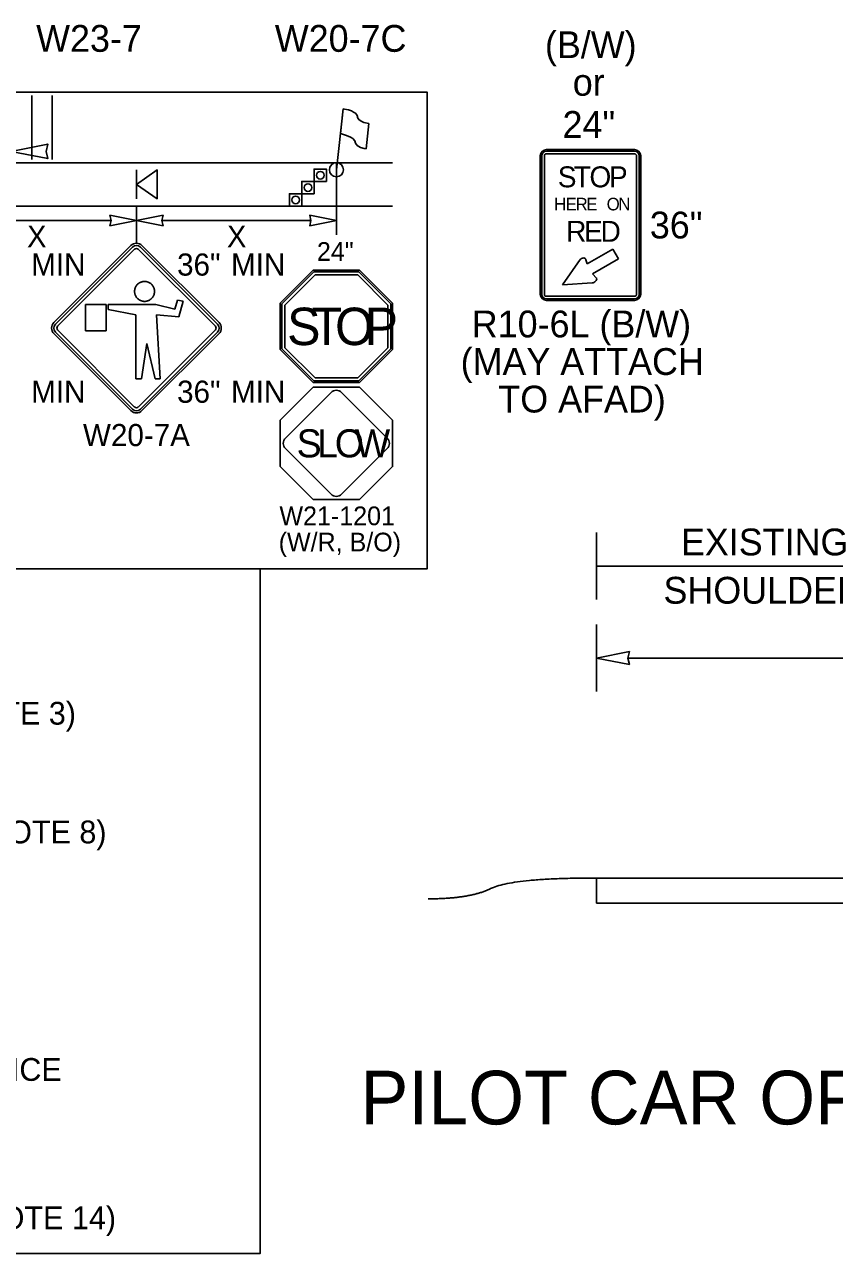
# Model space of a CAD drawing. Extents: x 99999.1 to 100095.7, y 99995 to 100010.7.
# Drawn here: x 100042.586 to 100045, y 100001.176 to 100004.84 of the extents above; entities that cross this region are included whole.
import ezdxf

# ---------------------------------------------------------------- set-up
doc = ezdxf.new("R2010")
doc.units = 0
for name, color, linetype in [('RD_ED_ShoulderPavedEdge', 7, 'Continuous'), ('RD_MK_LineEdgeWhite', 7, 'Continuous'), ('SH_DE_DetailHeading1Text', 7, 'Continuous'), ('TR_SN_ConstructionSigns', 7, 'Continuous'), ('TR_WZ_FlaggingStation', 7, 'Continuous'), ('TR_WZ_PortableSignMountBlk-Org', 7, 'Continuous'), ('TR_WZ_TrafficCone', 7, 'Continuous'), ('TR_WZ_WorkZoneDetails', 7, 'Continuous'), ('TR_WZ_WorkZoneTextCurrent', 7, 'Continuous')]:
    doc.layers.add(name, color=color, linetype=linetype)

msp = doc.modelspace()

# ---------------------------------------------------------------- linework, layer by layer
at = {"layer": 'RD_ED_ShoulderPavedEdge'}
msp.add_line((100040.2, 100004.2992), (100043.6825, 100004.2992), dxfattribs=at)
at = {"layer": 'RD_MK_LineEdgeWhite'}
msp.add_line((100040.2, 100004.4284), (100043.6825, 100004.4284), dxfattribs=at)
at = {"layer": 'TR_SN_ConstructionSigns'}
for p, q in [((100044.4041, 100004.4676), (100044.1416, 100004.4676)), ((100044.1416, 100004.4676), (100044.4041, 100004.4676)), ((100044.4041, 100004.4676), (100044.1416, 100004.4676)), ((100044.1229, 100004.4489), (100044.1229, 100004.0364)), ((100044.1229, 100004.0364), (100044.1229, 100004.4489)), ((100044.1229, 100004.4489), (100044.1229, 100004.0364)), ((100044.1276, 100004.4489), (100044.1276, 100004.0364)), ((100044.1354, 100004.0364), (100044.1354, 100004.4489)), ((100044.4041, 100004.4629), (100044.1416, 100004.4629)), ((100044.1416, 100004.4551), (100044.4041, 100004.4551)), ((100044.4104, 100004.4489), (100044.4104, 100004.0364)), ((100044.4182, 100004.0364), (100044.4182, 100004.4489)), ((100044.4229, 100004.0364), (100044.4229, 100004.4489)), ((100044.4229, 100004.4489), (100044.4229, 100004.0364)), ((100044.4229, 100004.0364), (100044.4229, 100004.4489)), ((100042.9031, 100004.1813), (100042.6734, 100003.9516)), ((100042.9076, 100004.1768), (100042.6779, 100003.9471)), ((100043.161, 100003.9471), (100042.9313, 100004.1768)), ((100043.1656, 100003.9516), (100042.9359, 100004.1813)), ((100044.3396, 100004.1707), (100044.263, 100004.1265)), ((100044.356, 100004.1423), (100044.3396, 100004.1707)), ((100042.6843, 100003.9407), (100042.914, 100004.1704)), ((100042.9249, 100004.1704), (100043.1546, 100003.9407)), ((100044.2424, 100004.1403), (100044.1898, 100004.0646)), ((100044.263, 100004.1265), (100044.2592, 100004.1391)), ((100044.2786, 100004.0976), (100044.356, 100004.1423)), ((100043.446, 100004.1079), (100043.3479, 100004.0098)), ((100043.4482, 100004.1026), (100043.3531, 100004.0076)), ((100043.5847, 100004.1079), (100043.446, 100004.1079)), ((100043.5825, 100004.1026), (100043.4482, 100004.1026)), ((100043.6775, 100004.0076), (100043.5825, 100004.1026)), ((100043.6828, 100004.0098), (100043.5847, 100004.1079)), ((100044.2909, 100004.0839), (100044.2786, 100004.0976)), ((100042.9188, 100004.0612), (100042.9179, 100004.0598)), ((100042.9197, 100004.0625), (100042.9188, 100004.0612)), ((100042.9207, 100004.0637), (100042.9197, 100004.0625)), ((100042.9217, 100004.0649), (100042.9207, 100004.0637)), ((100042.9228, 100004.066), (100042.9217, 100004.0649)), ((100042.924, 100004.0671), (100042.9228, 100004.066)), ((100042.9252, 100004.0681), (100042.924, 100004.0671)), ((100042.9264, 100004.069), (100042.9252, 100004.0681)), ((100042.9278, 100004.0699), (100042.9264, 100004.069)), ((100042.9291, 100004.0707), (100042.9278, 100004.0699)), ((100042.9306, 100004.0714), (100042.9291, 100004.0707)), ((100042.932, 100004.0721), (100042.9306, 100004.0714)), ((100042.9335, 100004.0727), (100042.932, 100004.0721)), ((100042.935, 100004.0731), (100042.9335, 100004.0727)), ((100042.9365, 100004.0736), (100042.935, 100004.0731)), ((100042.9381, 100004.0739), (100042.9365, 100004.0736)), ((100042.9396, 100004.0742), (100042.9381, 100004.0739)), ((100042.9412, 100004.0743), (100042.9396, 100004.0742)), ((100042.9428, 100004.0744), (100042.9412, 100004.0743)), ((100042.9444, 100004.0744), (100042.9428, 100004.0744)), ((100042.9459, 100004.0743), (100042.9444, 100004.0744)), ((100042.9475, 100004.0742), (100042.9459, 100004.0743)), ((100042.949, 100004.0739), (100042.9475, 100004.0742)), ((100042.9506, 100004.0736), (100042.949, 100004.0739)), ((100042.9521, 100004.0731), (100042.9506, 100004.0736)), ((100042.9536, 100004.0727), (100042.9521, 100004.0731)), ((100042.9551, 100004.0721), (100042.9536, 100004.0727)), ((100042.9565, 100004.0714), (100042.9551, 100004.0721)), ((100042.9579, 100004.0707), (100042.9565, 100004.0714)), ((100042.9593, 100004.0699), (100042.9579, 100004.0707)), ((100042.9606, 100004.069), (100042.9593, 100004.0699)), ((100042.9619, 100004.0681), (100042.9606, 100004.069)), ((100042.9631, 100004.0671), (100042.9619, 100004.0681)), ((100042.9643, 100004.066), (100042.9631, 100004.0671)), ((100042.9654, 100004.0649), (100042.9643, 100004.066)), ((100042.9664, 100004.0637), (100042.9654, 100004.0649)), ((100042.9674, 100004.0625), (100042.9664, 100004.0637)), ((100042.9683, 100004.0612), (100042.9674, 100004.0625)), ((100042.9691, 100004.0598), (100042.9683, 100004.0612)), ((100043.3619, 100004.004), (100043.4518, 100004.0939)), ((100043.4518, 100004.0939), (100043.5789, 100004.0939)), ((100043.5789, 100004.0939), (100043.6688, 100004.004)), ((100044.1898, 100004.0646), (100044.2776, 100004.0707)), ((100042.914, 100004.0479), (100042.9138, 100004.0463)), ((100042.9138, 100004.0463), (100042.9138, 100004.0447)), ((100042.9138, 100004.0447), (100042.9138, 100004.0432)), ((100042.9138, 100004.0432), (100042.914, 100004.0416)), ((100042.9142, 100004.0495), (100042.914, 100004.0479)), ((100042.914, 100004.0416), (100042.9142, 100004.04)), ((100042.9145, 100004.051), (100042.9142, 100004.0495)), ((100042.9142, 100004.04), (100042.9145, 100004.0385)), ((100042.9149, 100004.0525), (100042.9145, 100004.051)), ((100042.9145, 100004.0385), (100042.9149, 100004.0369)), ((100042.9153, 100004.054), (100042.9149, 100004.0525)), ((100042.9149, 100004.0369), (100042.9153, 100004.0354)), ((100042.9159, 100004.0555), (100042.9153, 100004.054)), ((100042.9153, 100004.0354), (100042.9159, 100004.0339)), ((100042.9165, 100004.057), (100042.9159, 100004.0555)), ((100042.9159, 100004.0339), (100042.9165, 100004.0324)), ((100042.9171, 100004.0584), (100042.9165, 100004.057)), ((100042.9165, 100004.0324), (100042.9171, 100004.031)), ((100042.9179, 100004.0598), (100042.9171, 100004.0584)), ((100042.9171, 100004.031), (100042.9179, 100004.0296)), ((100042.9179, 100004.0296), (100042.9188, 100004.0283)), ((100042.9188, 100004.0283), (100042.9197, 100004.027)), ((100042.9197, 100004.027), (100042.9207, 100004.0258)), ((100042.9207, 100004.0258), (100042.9217, 100004.0246)), ((100042.9217, 100004.0246), (100042.9228, 100004.0234)), ((100042.9643, 100004.0234), (100042.9654, 100004.0246)), ((100042.9654, 100004.0246), (100042.9664, 100004.0258)), ((100042.9664, 100004.0258), (100042.9674, 100004.027)), ((100042.9674, 100004.027), (100042.9683, 100004.0283)), ((100042.9683, 100004.0283), (100042.9691, 100004.0296)), ((100042.9699, 100004.0584), (100042.9691, 100004.0598)), ((100042.9691, 100004.0296), (100042.9699, 100004.031)), ((100042.9706, 100004.057), (100042.9699, 100004.0584)), ((100042.9699, 100004.031), (100042.9706, 100004.0324)), ((100042.9712, 100004.0555), (100042.9706, 100004.057)), ((100042.9706, 100004.0324), (100042.9712, 100004.0339)), ((100042.9718, 100004.054), (100042.9712, 100004.0555)), ((100042.9712, 100004.0339), (100042.9718, 100004.0354)), ((100042.9722, 100004.0525), (100042.9718, 100004.054)), ((100042.9718, 100004.0354), (100042.9722, 100004.0369)), ((100042.9726, 100004.051), (100042.9722, 100004.0525)), ((100042.9722, 100004.0369), (100042.9726, 100004.0385)), ((100042.9729, 100004.0495), (100042.9726, 100004.051)), ((100042.9726, 100004.0385), (100042.9729, 100004.04)), ((100042.9731, 100004.0479), (100042.9729, 100004.0495)), ((100042.9729, 100004.04), (100042.9731, 100004.0416)), ((100042.9732, 100004.0463), (100042.9731, 100004.0479)), ((100042.9731, 100004.0416), (100042.9732, 100004.0432)), ((100042.9733, 100004.0447), (100042.9732, 100004.0463)), ((100042.9732, 100004.0432), (100042.9733, 100004.0447)), ((100044.4041, 100004.0301), (100044.1416, 100004.0301)), ((100042.7675, 100004.0057), (100042.7675, 100003.9275)), ((100042.8296, 100004.0057), (100042.7675, 100004.0057)), ((100042.8296, 100003.9275), (100042.8296, 100004.0057)), ((100042.9768, 100004.0057), (100042.8354, 100004.0057)), ((100042.8354, 100004.0057), (100042.8354, 100003.9908)), ((100042.8354, 100003.9908), (100042.9175, 100003.9745)), ((100042.9228, 100004.0234), (100042.924, 100004.0224)), ((100042.924, 100004.0224), (100042.9252, 100004.0214)), ((100042.9252, 100004.0214), (100042.9264, 100004.0204)), ((100042.9264, 100004.0204), (100042.9278, 100004.0195)), ((100042.9278, 100004.0195), (100042.9291, 100004.0187)), ((100042.9291, 100004.0187), (100042.9306, 100004.018)), ((100042.9306, 100004.018), (100042.932, 100004.0173)), ((100042.932, 100004.0173), (100042.9335, 100004.0168)), ((100042.9335, 100004.0168), (100042.935, 100004.0163)), ((100042.935, 100004.0163), (100042.9365, 100004.0158)), ((100042.9365, 100004.0158), (100042.9381, 100004.0155)), ((100042.9381, 100004.0155), (100042.9396, 100004.0153)), ((100042.9396, 100004.0153), (100042.9412, 100004.0151)), ((100042.9412, 100004.0151), (100042.9428, 100004.015)), ((100042.9428, 100004.015), (100042.9444, 100004.015)), ((100042.9444, 100004.015), (100042.9459, 100004.0151)), ((100042.9459, 100004.0151), (100042.9475, 100004.0153)), ((100042.9475, 100004.0153), (100042.949, 100004.0155)), ((100042.949, 100004.0155), (100042.9506, 100004.0158)), ((100042.9506, 100004.0158), (100042.9521, 100004.0163)), ((100042.9521, 100004.0163), (100042.9536, 100004.0168)), ((100042.9536, 100004.0168), (100042.9551, 100004.0173)), ((100042.9551, 100004.0173), (100042.9565, 100004.018)), ((100042.9565, 100004.018), (100042.9579, 100004.0187)), ((100042.9579, 100004.0187), (100042.9593, 100004.0195)), ((100042.9593, 100004.0195), (100042.9606, 100004.0204)), ((100042.9606, 100004.0204), (100042.9619, 100004.0214)), ((100042.9619, 100004.0214), (100042.9631, 100004.0224)), ((100042.9631, 100004.0224), (100042.9643, 100004.0234)), ((100043.0341, 100003.9915), (100042.9768, 100004.0057)), ((100043.0421, 100004.0186), (100043.0341, 100003.9915)), ((100043.0586, 100004.0157), (100043.0421, 100004.0186)), ((100043.0462, 100003.9688), (100043.0586, 100004.0157)), ((100043.3479, 100004.0098), (100043.3479, 100003.8711)), ((100043.3531, 100004.0076), (100043.3531, 100003.8733)), ((100043.3619, 100003.8769), (100043.3619, 100004.004)), ((100043.6688, 100004.004), (100043.6688, 100003.8769)), ((100043.6775, 100003.8733), (100043.6775, 100004.0076)), ((100043.6828, 100003.8711), (100043.6828, 100004.0098)), ((100044.1416, 100004.0223), (100044.4041, 100004.0223)), ((100044.1416, 100004.0176), (100044.4041, 100004.0176)), ((100044.4041, 100004.0176), (100044.1416, 100004.0176)), ((100044.1416, 100004.0176), (100044.4041, 100004.0176)), ((100042.9175, 100003.9745), (100042.9175, 100003.7844)), ((100042.9902, 100003.7844), (100042.9794, 100003.9745)), ((100042.9794, 100003.9745), (100043.0462, 100003.9688)), ((100042.6734, 100003.9188), (100042.9031, 100003.6891)), ((100042.6779, 100003.9234), (100042.9076, 100003.6937)), ((100042.914, 100003.7), (100042.6843, 100003.9297)), ((100042.7675, 100003.9275), (100042.8296, 100003.9275)), ((100043.1546, 100003.9297), (100042.9249, 100003.7)), ((100042.9313, 100003.6937), (100043.161, 100003.9234)), ((100042.9359, 100003.6891), (100043.1656, 100003.9188)), ((100042.9341, 100003.7844), (100042.9503, 100003.8889)), ((100042.9503, 100003.8889), (100042.9753, 100003.7844)), ((100043.3479, 100003.8711), (100043.446, 100003.773)), ((100043.3531, 100003.8733), (100043.4482, 100003.7783)), ((100043.4518, 100003.787), (100043.3619, 100003.8769)), ((100043.6688, 100003.8769), (100043.5789, 100003.787)), ((100043.5825, 100003.7783), (100043.6775, 100003.8733)), ((100043.5847, 100003.773), (100043.6828, 100003.8711)), ((100042.9175, 100003.7844), (100042.9341, 100003.7844)), ((100042.9753, 100003.7844), (100042.9902, 100003.7844)), ((100043.446, 100003.773), (100043.5847, 100003.773)), ((100043.4482, 100003.7783), (100043.5825, 100003.7783)), ((100043.5789, 100003.787), (100043.4518, 100003.787)), ((100043.4996, 100003.7433), (100043.3637, 100003.6074)), ((100043.667, 100003.6074), (100043.5311, 100003.7433)), ((100043.3637, 100003.5759), (100043.4996, 100003.44)), ((100043.5311, 100003.44), (100043.667, 100003.5759))]:
    msp.add_line(p, q, dxfattribs=at)
msp.add_lwpolyline([(100043.6828, 100003.661), (100043.6828, 100003.5223), (100043.5847, 100003.4242), (100043.446, 100003.4242), (100043.3479, 100003.5223), (100043.3479, 100003.661), (100043.446, 100003.7591), (100043.5847, 100003.7591)], close=True, dxfattribs=at)
for centre, radius, start, end in [((100044.1416, 100004.4489), 0.0187, 90, 180), ((100044.1416, 100004.4489), 0.0187, 90, 180), ((100044.1416, 100004.4489), 0.0187, 90, 180), ((100044.4041, 100004.4489), 0.0187, 0, 90), ((100044.4041, 100004.4489), 0.0187, 0, 90), ((100044.4041, 100004.4489), 0.0187, 0, 90), ((100044.1416, 100004.4489), 0.0141, 90, 180), ((100044.1416, 100004.4489), 0.00625, 90, 180), ((100044.4041, 100004.4489), 0.0141, 0, 90), ((100044.4041, 100004.4489), 0.00625, 0, 90), ((100042.9195, 100004.1649), 0.0232, 45, 135), ((100042.9195, 100004.1649), 0.0168, 45, 135), ((100042.9195, 100004.1649), 0.00773, 45, 135), ((100044.1416, 100004.0364), 0.0187, 180, 270), ((100044.1416, 100004.0364), 0.0187, 180, 270), ((100044.1416, 100004.0364), 0.0187, 180, 270), ((100044.1416, 100004.0364), 0.0141, 180, 270), ((100044.1416, 100004.0364), 0.00625, 180, 270), ((100044.4041, 100004.0364), 0.0187, 270, 0), ((100044.4041, 100004.0364), 0.0187, 270, 0), ((100044.4041, 100004.0364), 0.0187, 270, 0), ((100044.4041, 100004.0364), 0.0141, 270, 0), ((100044.4041, 100004.0364), 0.00625, 270, 0), ((100042.6898, 100003.9352), 0.0232, 135, 225), ((100043.1492, 100003.9352), 0.0232, 315, 45), ((100042.6898, 100003.9352), 0.0168, 135, 225), ((100042.6898, 100003.9352), 0.00773, 135, 225), ((100043.1492, 100003.9352), 0.00773, 315, 45), ((100043.1492, 100003.9352), 0.0168, 315, 45), ((100043.5153, 100003.7275), 0.0223, 45, 135), ((100042.9195, 100003.7055), 0.00773, 225, 315), ((100042.9195, 100003.7055), 0.0232, 225, 315), ((100042.9195, 100003.7055), 0.0168, 225, 315), ((100043.3795, 100003.5916), 0.0223, 135, 225), ((100043.6512, 100003.5916), 0.0223, 315, 45), ((100043.5153, 100003.4558), 0.0223, 225, 315)]:
    msp.add_arc(centre, radius, start, end, dxfattribs=at)
for centre, major_axis, start_param, end_param in [((100044.2492, 100004.136), (0.00934, 0.00539), 5.977036, 8.198856), ((100044.2816, 100004.0789), (-0.00913, -0.00527), 0.771965, 3.092601)]:
    msp.add_ellipse(centre, major_axis=major_axis, ratio=0.700347, start_param=start_param, end_param=end_param, dxfattribs=at)
at = {"layer": 'TR_WZ_FlaggingStation'}
for p, q in [((100043.5154, 100004.4074), (100043.5361, 100004.5889)), ((100043.5277, 100004.5152), (100043.5361, 100004.5891)), ((100043.6123, 100004.5453), (100043.6037, 100004.4696)), ((100043.5277, 100004.5152), (100043.5277, 100004.5152))]:
    msp.add_line(p, q, dxfattribs=at)
for points in [[(100043.5361, 100004.5891), (100043.5398, 100004.5883), (100043.5514, 100004.5861), (100043.5603, 100004.5834), (100043.5665, 100004.5794), (100043.5721, 100004.5764), (100043.5757, 100004.572), (100043.5785, 100004.5669), (100043.5788, 100004.5629), (100043.5823, 100004.557), (100043.5892, 100004.5522), (100043.5973, 100004.5488), (100043.6123, 100004.5453)], [(100043.6037, 100004.4696), (100043.5985, 100004.4705), (100043.587, 100004.4735), (100043.5769, 100004.4803), (100043.5727, 100004.4871), (100043.5702, 100004.4938), (100043.5643, 100004.5008), (100043.5572, 100004.5048), (100043.546, 100004.5094), (100043.5277, 100004.5152)]]:
    msp.add_lwpolyline(points, dxfattribs=at)
msp.add_circle((100043.5154, 100004.4074), 0.021, dxfattribs=at)
at = {"layer": 'TR_WZ_PortableSignMountBlk-Org'}
msp.add_line((100042.9195, 100004.3208), (100042.9195, 100004.4069), dxfattribs=at)
msp.add_lwpolyline([(100042.9195, 100004.3638), (100042.9813, 100004.4069), (100042.9813, 100004.3208)], close=True, dxfattribs=at)
at = {"layer": 'TR_WZ_TrafficCone'}
for points in [[(100043.4491, 100004.4095), (100043.4858, 100004.4095), (100043.4858, 100004.3727), (100043.4491, 100004.3727), (100043.4491, 100004.4095)], [(100043.4491, 100004.3727), (100043.4858, 100004.3727), (100043.4858, 100004.4095), (100043.4491, 100004.4095), (100043.4491, 100004.3727)], [(100043.4123, 100004.3727), (100043.4491, 100004.3727), (100043.4491, 100004.336), (100043.4123, 100004.336), (100043.4123, 100004.3727)], [(100043.4123, 100004.336), (100043.4491, 100004.336), (100043.4491, 100004.3727), (100043.4123, 100004.3727), (100043.4123, 100004.336)], [(100043.3756, 100004.336), (100043.4123, 100004.336), (100043.4123, 100004.2992), (100043.3756, 100004.2992), (100043.3756, 100004.336)], [(100043.3756, 100004.2992), (100043.4123, 100004.2992), (100043.4123, 100004.336), (100043.3756, 100004.336), (100043.3756, 100004.2992)]]:
    msp.add_lwpolyline(points, dxfattribs=at)
for centre in [(100043.4674, 100004.3911), (100043.4307, 100004.3544), (100043.3939, 100004.3176)]:
    msp.add_circle(centre, 0.0115, dxfattribs=at)
at = {"layer": 'TR_WZ_WorkZoneDetails'}
for p, q in [((100042.6076, 100004.4384), (100042.6076, 100004.6291)), ((100042.6686, 100004.4384), (100042.6686, 100004.6291)), ((100043.5154, 100004.4284), (100043.5154, 100004.2131)), ((100042.9195, 100004.2992), (100042.9195, 100004.1881)), ((100042.8438, 100004.2562), (100042.3992, 100004.2562)), ((100043.4397, 100004.2562), (100042.9952, 100004.2562)), ((100044.2907, 100003.1255), (100044.2907, 100003.3255)), ((100044.2907, 100003.2255), (100045.2907, 100003.2255)), ((100044.2907, 100002.8515), (100044.2907, 100003.0515)), ((100046.397, 100002.9515), (100044.3844, 100002.9515)), ((100044.2907, 100002.2954), (100044.2907, 100002.2204)), ((100048.6907, 100002.2954), (100044.2907, 100002.2954)), ((100048.6907, 100002.2204), (100044.2907, 100002.2204))]:
    msp.add_line(p, q, dxfattribs=at)
for points in [[(100042.5458, 100004.4624), (100042.655, 100004.441), (100042.6499, 100004.4624), (100042.655, 100004.4838)], [(100042.9195, 100004.2562), (100042.8401, 100004.2717), (100042.8438, 100004.2562), (100042.8401, 100004.2406)], [(100042.9195, 100004.2562), (100042.9988, 100004.2717), (100042.9952, 100004.2562), (100042.9988, 100004.2406)], [(100043.5154, 100004.2562), (100043.4361, 100004.2717), (100043.4397, 100004.2562), (100043.4361, 100004.2406)], [(100044.2907, 100002.9515), (100044.389, 100002.9322), (100044.3844, 100002.9515), (100044.389, 100002.9708)]]:
    msp.add_lwpolyline(points, close=True, dxfattribs=at)
msp.add_open_spline([(100044.2907, 100002.2954), (100044.0395, 100002.2954), (100043.914, 100002.2333), (100043.7886, 100002.2333)], degree=2, dxfattribs=at)
at = {"layer": 'TR_WZ_WorkZoneTextCurrent'}
for points in [[(100040.1, 100004.6391), (100043.7858, 100004.6391), (100043.7858, 100003.2174), (100040.1, 100003.2174)], [(100040.1, 100003.2174), (100043.2886, 100003.2174), (100043.2886, 100001.1759), (100040.1, 100001.1759)]]:
    msp.add_lwpolyline(points, close=True, dxfattribs=at)

# ---------------------------------------------------------------- texts
at = {"layer": 'SH_DE_DetailHeading1Text'}
msp.add_text('PILOT CAR OPERATION FOR ALTERNATING 1-LANE, 2-WAY TRAFFIC: AFAD-CONTROLLED + TEMP. RUMBLE STRIPS', height=0.16, rotation=360, dxfattribs=at).set_placement((100043.5872, 100001.5606))
at = {"layer": 'TR_SN_ConstructionSigns'}
for s, height, p in [('W23-7', 0.08, (100042.6204, 100004.7592)), ('W20-7C', 0.08, (100043.3319, 100004.7592)), ('(B/W)', 0.08, (100044.1371, 100004.7403)), ('or', 0.08, (100044.2201, 100004.6283)), ('24"', 0.08, (100044.1895, 100004.5026)), ('36"', 0.08, (100044.4498, 100004.2026)), ('MIN', 0.066, (100042.6055, 100004.0918)), ('36"', 0.066, (100043.0405, 100004.0918)), ('MIN', 0.066, (100043.2014, 100004.0918)), ('R10-6L (B/W)', 0.08, (100043.919, 100003.9076)), ('(MAY ATTACH', 0.08, (100043.8858, 100003.7956)), ('MIN', 0.066, (100042.6055, 100003.7126)), ('36"', 0.066, (100043.0405, 100003.7126)), ('MIN', 0.066, (100043.2014, 100003.7126)), ('TO AFAD)', 0.08, (100043.9982, 100003.6836)), ('W20-7A', 0.066, (100042.76, 100003.5833)), ('W21-1201', 0.05581, (100043.3457, 100003.3475)), ('(W/R, B/O)', 0.05581, (100043.3434, 100003.2694))]:
    msp.add_text(s, height=height, rotation=360, dxfattribs=at).set_placement(p)
for s, height, p in [('S', 0.0625, (100044.1754, 100004.3551)), ('T', 0.0625, (100044.2229, 100004.3551)), ('O', 0.0625, (100044.2698, 100004.3551)), ('P', 0.0625, (100044.3279, 100004.3551)), ('H', 0.0375, (100044.1643, 100004.2864)), ('E', 0.0375, (100044.1988, 100004.2864)), ('R', 0.0375, (100044.2284, 100004.2864)), ('E', 0.0375, (100044.2603, 100004.2864)), ('O', 0.0375, (100044.3211, 100004.2864)), ('N', 0.0375, (100044.3559, 100004.2864)), ('R', 0.0625, (100044.2004, 100004.1926)), ('E', 0.0625, (100044.2535, 100004.1926)), ('D', 0.0625, (100044.3029, 100004.1926)), ('24"', 0.05581, (100043.4574, 100004.1358)), ('S', 0.1116, (100043.3686, 100003.8846)), ('T', 0.1116, (100043.4411, 100003.8846)), ('O', 0.1116, (100043.5114, 100003.8846)), ('P', 0.1116, (100043.5996, 100003.8846)), ('S', 0.0837, (100043.3969, 100003.5498)), ('L', 0.0837, (100043.458, 100003.5498)), ('O', 0.0837, (100043.5107, 100003.5498)), ('W', 0.0837, (100043.5702, 100003.5498))]:
    msp.add_text(s, height=height, dxfattribs=at).set_placement(p)
at = {"layer": 'TR_WZ_WorkZoneDetails'}
for s, p in [('EXISTING', (100044.5424, 100003.2575)), ('SHOULDER', (100044.4905, 100003.1135))]:
    msp.add_text(s, height=0.08, rotation=360, dxfattribs=at).set_placement(p)
at = {"layer": 'TR_WZ_WorkZoneTextCurrent'}
for p in [(100042.5935, 100004.1765), (100043.1894, 100004.1765)]:
    msp.add_text('X', height=0.0646, dxfattribs=at).set_placement(p)
for s, p in [('28" REFLECTIVE TRAFFIC CONE (SEE NOTE 3)', (100040.7009, 100002.7527)), ('28" PORTABLE TUBULAR MARKER (SEE NOTE 8)', (100040.7009, 100002.3987)), ('AUTOMATED FLAGGER ASSISTANCE DEVICE', (100040.7009, 100001.6905)), ('TEMP. PORTABLE RUMBLE STRIP (SEE NOTE 14)', (100040.7009, 100001.2479))]:
    msp.add_text(s, height=0.068, rotation=360, dxfattribs=at).set_placement(p)

doc.saveas('drawing.dxf')
